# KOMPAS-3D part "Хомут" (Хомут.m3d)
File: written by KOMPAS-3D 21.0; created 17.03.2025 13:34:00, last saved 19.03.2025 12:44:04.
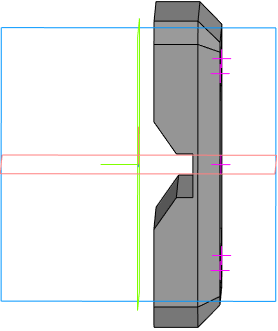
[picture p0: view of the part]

Document properties: Автор: fedorov478@gmail.com; Полное имя файла: C:\Users\User\Desktop\Ринат все\Ринат\Перспектива\Хомут.m3d

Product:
- Part/product: Хомут
    Масса: 0.240541

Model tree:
1. Эскиз:5
2. Элемент выдавливания:9
     Расстояние 1 = 60
3. Эскиз:6  (with: Элемент выдавливания:9)
4. Отверстие:1  (with: Элемент выдавливания:9)
     Глубина выреза = 21; Диаметр отверстия = 6; Угол конуса дна = 118; Расстояние 1 = 50; Расстояние 2 = 46; Диаметр цековки = 10; Глубина цековки = 7
5. M6  (with: Элемент выдавливания:9)  (labels: cil0_24705-2004 coarse)
     Длина резьбы = 19; Шаг резьбы = 1; Номинальный диаметр резьбы = 6
6. Массив по точкам:1
7. Экземпляр ( 3 )  (with: Отверстие:1, Эскиз:6)
8. Экземпляр ( 2 )  (with: Отверстие:1, Эскиз:6)
9. Экземпляр ( 1 )  (with: Отверстие:1, Эскиз:6)
10. Фаска:1  (with: Элемент выдавливания:9)
     Угол = 45; Длина 1 = 4; Длина 2 = 4
11. Фаска:4  (with: Фаска:1, Элемент выдавливания:9)
     Угол = 45; Длина 1 = 4; Длина 2 = 4

Expressions: v713*2; v927/2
